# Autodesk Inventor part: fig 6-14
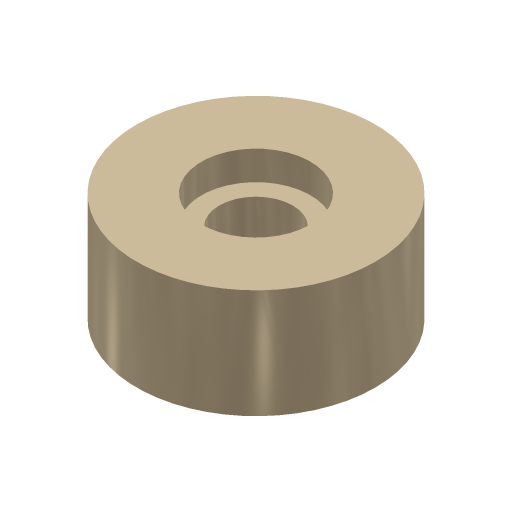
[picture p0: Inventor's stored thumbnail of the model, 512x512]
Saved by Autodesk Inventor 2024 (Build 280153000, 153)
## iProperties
Shininess: 65.0
Angle Display Precision: 2
Document Length Units: 11269
Document Angle Units: 11279
Document Time Units: 11290
Document Mass Units: 11283
Document Length Units Precision: 3
Document Angle Units Precision: 2
Created: 2001-11
Part Number: fig 6-14
Document SubType Name: Modeling
Designer: Renu Muthoo
Density: 1 g/cm^3
Material: Generic
Appearance: Metal-Titanium (Polished)
Density: 0.0
Volumn: 0.0
Area: 0.0
PropertySet Name: Model Information
Control State: 0
Master: False
Checked Out: False
Author: Renu Muthoo
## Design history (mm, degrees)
sketch "Sketch1"
  geometry: C1 r 16.401 at (0, 0)
  constraints: 1 centre point
extrude "Extrusion1" new body sketch "Sketch1" distance "d0" = 15; taper "d1" = 0 deg
hole "Hole3" diameter "d18" = 10.106; stored, may be unused: countersink angle "d22" = 90 deg, drill point angle "d24" = 118 deg; dims "d16" = 10, "d17" = 10, "d19" = 6, "d20" = 15, "d21" = 4, "d23" = 10
body "Solid1"
